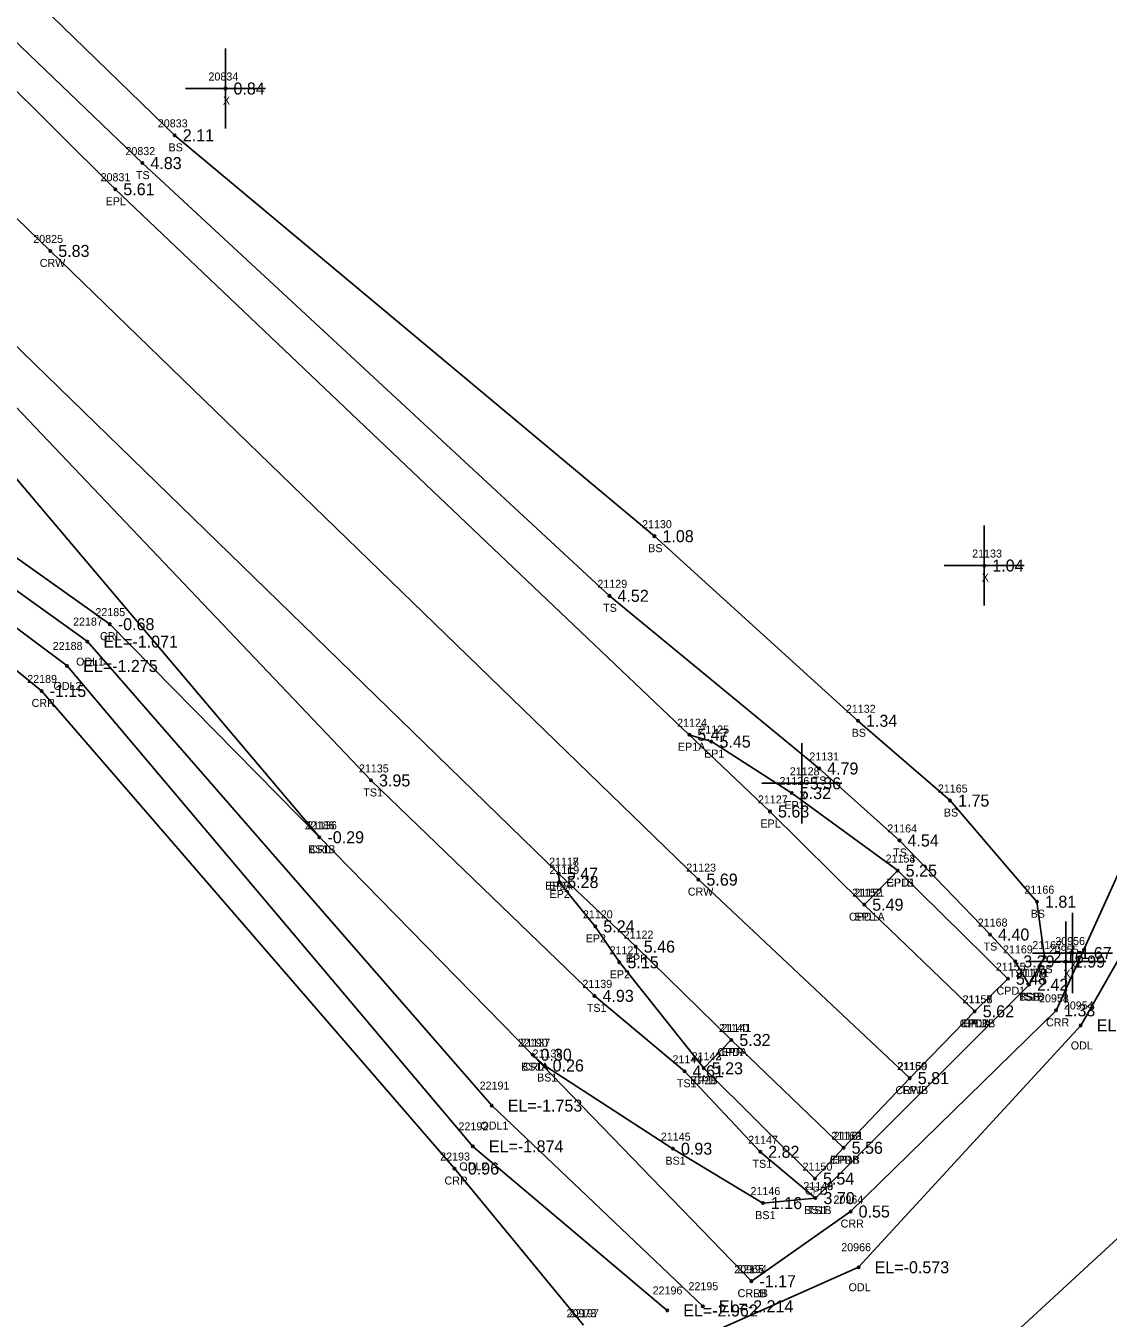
# Model space of a CAD drawing. Extents: x 2608745 to 2610333, y 641917 to 643463.
# Drawn here: x 2609407.7 to 2609542.9, y 642665.2 to 642826.6 of the extents above; entities that cross this region are included whole.
import ezdxf

# ---------------------------------------------------------------- set-up
doc = ezdxf.new("R2010")
doc.units = 0
for name, color, linetype in [('RD_DTM_BkLn1', 7, 'Continuous'), ('RD_DTM_BkLn2', 7, 'Continuous'), ('RD_DTM_BkLn_txCode', 7, 'Continuous'), ('RD_EX_Conc', 7, 'Continuous'), ('RD_EX_Conc_txCode', 7, 'Continuous'), ('RD_EX_H2O', 7, 'Continuous'), ('RD_EX_H2O_txCode', 7, 'Continuous'), ('RD_EX_Misc', 7, 'Continuous'), ('RD_EX_Misc_txCode', 7, 'Continuous'), ('RD_EX_Road', 7, 'Continuous'), ('RD_EX_Road_txCode', 7, 'Continuous'), ('RD_EX_TX_Conc_ELEV', 7, 'Continuous'), ('RD_EX_TX_H2O_ELEV', 7, 'Continuous'), ('RD_EX_TX_Misc_ELEV', 7, 'Continuous'), ('RD_EX_TX_Road_ELEV', 7, 'Continuous'), ('RD_HC_Survey_ELEV', 7, 'Continuous'), ('RD_HC_Survey_txCode', 7, 'Continuous'), ('RD_SMD_Locator', 7, 'Continuous')]:
    doc.layers.add(name, color=color, linetype=linetype)

msp = doc.modelspace()

# ---------------------------------------------------------------- linework, layer by layer
at = {"layer": 'RD_DTM_BkLn1'}
msp.add_lwpolyline([(2608814.73, 643373.65), (2608890.45, 643300.26), (2608962.19, 643231.31), (2609034.91, 643161.19), (2609108.48, 643089.9), (2609179.19, 643022.29), (2609255.71, 642948.78), (2609335.19, 642871.73), (2609410.7, 642798.48), (2609491.67, 642719.95), (2609518.07, 642695.15)], dxfattribs=at)
at = {"layer": 'RD_DTM_BkLn2'}
for points in [[(2609298.5, 642957.84), (2609303.58, 642944.57), (2609301.78, 642940.67), (2609288.09, 642950.22), (2609286.42, 642948.37), (2609286.98, 642943.32), (2609297.07, 642935.45), (2609305.3, 642928.41), (2609313.77, 642918.5), (2609346.23, 642882.3), (2609422.21, 642809.45), (2609480.56, 642755.4), (2609506.75, 642733.83), (2609516.79, 642724.84), (2609528.1, 642713.09), (2609531.25, 642709.73), (2609532.97, 642706.82)], [(2609299.18, 642957.88), (2609318.45, 642940.41), (2609325.58, 642932.79), (2609321.98, 642922.91), (2609316.71, 642922.45), (2609350.68, 642886.23), (2609426.26, 642812.92), (2609486.18, 642762.85), (2609511.6, 642739.79), (2609523.11, 642729.83), (2609533.96, 642717.19), (2609534.91, 642710.27), (2609532.97, 642706.82)], [(2609261.87, 642916.52), (2609266.58, 642914.91), (2609285.18, 642896.17), (2609323.43, 642858.86), (2609399.07, 642786.65), (2609450.77, 642732.34), (2609478.69, 642705.43), (2609489.94, 642696.01), (2609499.39, 642685.95), (2609506.29, 642680.17), (2609532.97, 642706.82)], [(2609260.59, 642912.35), (2609267.04, 642908.29), (2609268.14, 642909.06), (2609282.93, 642892.55), (2609320.01, 642855.03), (2609395.77, 642782.61), (2609444.33, 642725.24)], [(2609470.95, 642698.08), (2609472.46, 642696.73), (2609488.49, 642686.34), (2609499.72, 642679.54), (2609506.29, 642680.17)]]:
    msp.add_lwpolyline(points, dxfattribs=at)
at = {"layer": 'RD_EX_Conc'}
for points in [[(2609512.38, 642716.82), (2609516.56, 642721.08), (2609530.33, 642707.57), (2609526.19, 642703.5)], [(2609495.78, 642699.92), (2609492.33, 642696.38), (2609506.23, 642682.6), (2609509.81, 642686.45)]]:
    msp.add_lwpolyline(points, dxfattribs=at)
at = {"layer": 'RD_EX_H2O'}
for points in [[(2609918.81, 643009.04), (2609840.99, 642946.19), (2609752.78, 642894.89), (2609679.02, 642833.68), (2609605.53, 642770.83), (2609557.42, 642733.27), (2609539.43, 642701.73), (2609511.68, 642671.53), (2609423.05, 642632.06), (2609369.55, 642600.24), (2609327.57, 642579.96), (2609257.07, 642528.8), (2609194.6, 642443.8), (2609156.56, 642341.27)], [(2609920.46, 642991.11), (2609852.12, 642929.11), (2609767.83, 642874.99), (2609693.3, 642807.6), (2609634.08, 642753.09), (2609556.79, 642686.91), (2609524.97, 642657.54), (2609444.81, 642602.16), (2609373.09, 642552.33), (2609285.68, 642492.71), (2609230.49, 642411.33), (2609205.38, 642280.88)], [(2609601.98, 642935.78), (2609673.88, 642833.93), (2609600.06, 642773.78), (2609552.45, 642739.01), (2609536.34, 642703.62), (2609510.68, 642678.49), (2609498.28, 642669.79)], [(2609341.7, 642811.8), (2609348.04, 642813.82), (2609381.33, 642778.02), (2609418.14, 642751.86), (2609444.33, 642725.24), (2609470.95, 642698.08), (2609498.28, 642669.79)], [(2609341.7, 642811.8), (2609340.78, 642806.36), (2609373.72, 642772.7), (2609409.62, 642743.52), (2609461.2, 642683.86), (2609477.32, 642664.29)], [(2609341.7, 642811.8), (2609343.44, 642808.27), (2609375.68, 642774.38), (2609412.81, 642746.64), (2609463.49, 642686.63), (2609487.77, 642666.13)], [(2609341.7, 642811.8), (2609345.04, 642810.74), (2609378.85, 642775.89), (2609415.34, 642749.68), (2609465.85, 642691.72), (2609492.22, 642666.66)]]:
    msp.add_lwpolyline(points, dxfattribs=at)
at = {"layer": 'RD_EX_Misc'}
for p, q in [((2609432.59, 642813.77), (2609432.59, 642823.77)), ((2609427.59, 642818.77), (2609437.59, 642818.77)), ((2609527.38, 642754.18), (2609527.38, 642764.18)), ((2609522.38, 642759.18), (2609532.38, 642759.18)), ((2609504.59, 642726.98), (2609504.59, 642736.98)), ((2609499.59, 642731.98), (2609509.59, 642731.98)), ((2609537.56, 642704.71), (2609537.56, 642714.71)), ((2609538.39, 642705.78), (2609538.39, 642715.78)), ((2609533.39, 642710.78), (2609543.39, 642710.78)), ((2609532.56, 642709.71), (2609542.56, 642709.71))]:
    msp.add_line(p, q, dxfattribs=at)
at = {"layer": 'RD_EX_Road'}
for points in [[(2608806.89, 643364.99), (2608810.18, 643361.1), (2608820.75, 643351.25), (2608881.81, 643292.24), (2608917.83, 643257.49), (2608933.21, 643242.71), (2608954.07, 643222.83), (2609026.06, 643154.19), (2609039.6, 643139.96), (2609073.88, 643106.95), (2609100.48, 643081.89), (2609124.19, 643058.87), (2609171.61, 643013.71), (2609183.19, 643002.28), (2609197.91, 642988.37), (2609247.59, 642940.95), (2609328.02, 642863.6), (2609402.61, 642790.3), (2609474.23, 642720.69), (2609483.84, 642711.58), (2609495.78, 642699.92), (2609509.81, 642686.45)], [(2609058.51, 643155.46), (2609096.06, 643119.37), (2609116.51, 643099.11), (2609162.4, 643055.35), (2609177.21, 643041.34), (2609188.35, 643030.96), (2609199.91, 643019.76), (2609205.8, 643014.04), (2609217.13, 643003.17), (2609235.83, 642983.9), (2609237.03, 642983.51), (2609256.8, 642965.04), (2609258.49, 642962.51), (2609263.65, 642957.66), (2609344.71, 642879.89), (2609418.83, 642806.19), (2609500.61, 642728.46), (2609512.38, 642716.82), (2609526.19, 642703.5)], [(2609490.52, 642738.05), (2609493.3, 642737.2), (2609503.33, 642730.76), (2609516.56, 642721.08)], [(2609474.23, 642720.69), (2609474.28, 642719.65), (2609478.79, 642714.11), (2609481.8, 642709.62), (2609492.33, 642696.38)], [(2609526.19, 642703.5), (2609518.07, 642695.15), (2609509.81, 642686.45)]]:
    msp.add_lwpolyline(points, dxfattribs=at)
at = {"layer": 'RD_SMD_Locator'}
for centre in [(2609432.59, 642818.77), (2609426.26, 642812.92), (2609422.21, 642809.45), (2609418.83, 642806.19), (2609410.7, 642798.48), (2609486.18, 642762.85), (2609527.38, 642759.18), (2609480.56, 642755.4), (2609418.14, 642751.86), (2609415.34, 642749.68), (2609412.81, 642746.64), (2609409.62, 642743.52), (2609511.6, 642739.79), (2609490.52, 642738.05), (2609493.3, 642737.2), (2609450.77, 642732.34), (2609506.75, 642733.83), (2609503.33, 642730.76), (2609504.59, 642731.98), (2609523.11, 642729.83), (2609500.61, 642728.46), (2609444.33, 642725.24), (2609444.33, 642725.24), (2609516.79, 642724.84), (2609516.56, 642721.08), (2609516.56, 642721.08), (2609474.23, 642720.69), (2609474.23, 642720.69), (2609474.28, 642719.65), (2609491.67, 642719.95), (2609512.38, 642716.82), (2609512.38, 642716.82), (2609533.96, 642717.19), (2609478.79, 642714.11), (2609528.1, 642713.09), (2609483.84, 642711.58), (2609531.25, 642709.73), (2609534.91, 642710.27), (2609537.56, 642709.71), (2609538.39, 642710.78), (2609481.8, 642709.62), (2609530.33, 642707.57), (2609532.97, 642706.82), (2609532.97, 642706.82), (2609532.97, 642706.82), (2609478.69, 642705.43), (2609526.19, 642703.5), (2609526.19, 642703.5), (2609526.19, 642703.5), (2609536.34, 642703.62), (2609539.43, 642701.73), (2609495.78, 642699.92), (2609495.78, 642699.92), (2609470.95, 642698.08), (2609470.95, 642698.08), (2609472.46, 642696.73), (2609489.94, 642696.01), (2609492.33, 642696.38), (2609492.33, 642696.38), (2609518.07, 642695.15), (2609518.07, 642695.15), (2609465.85, 642691.72), (2609463.49, 642686.63), (2609488.49, 642686.34), (2609499.39, 642685.95), (2609509.81, 642686.45), (2609509.81, 642686.45), (2609509.81, 642686.45), (2609461.2, 642683.86), (2609506.23, 642682.6), (2609499.72, 642679.54), (2609506.29, 642680.17), (2609506.29, 642680.17), (2609510.68, 642678.49), (2609511.68, 642671.53), (2609498.28, 642669.79), (2609498.28, 642669.79), (2609487.77, 642666.13), (2609492.22, 642666.66)]:
    msp.add_circle(centre, 0.15, dxfattribs=at)

# ---------------------------------------------------------------- texts
at = {"layer": 'RD_DTM_BkLn_txCode'}
for s, p in [('20833', (2609424.14, 642813.92)), ('BS', (2609425.48, 642810.92)), ('20832', (2609420.09, 642810.45)), ('TS', (2609421.41, 642807.45)), ('21130', (2609484.63, 642763.85)), ('BS', (2609485.4, 642760.85)), ('21129', (2609479.05, 642756.4)), ('TS', (2609479.77, 642753.4)), ('21132', (2609510.09, 642740.79)), ('BS', (2609510.82, 642737.79)), ('21131', (2609505.52, 642734.83)), ('21135', (2609449.26, 642733.34)), ('TS', (2609505.95, 642731.83)), ('TS1', (2609449.81, 642730.34)), ('21165', (2609521.58, 642730.83)), ('BS', (2609522.33, 642727.83)), ('21136', (2609442.79, 642726.24)), ('21164', (2609515.26, 642725.84)), ('BS1B', (2609442.91, 642723.24)), ('TS', (2609516, 642722.84)), ('21166', (2609532.4, 642718.19)), ('21168', (2609526.56, 642714.09)), ('BS', (2609533.18, 642715.19)), ('TS', (2609527.3, 642711.09)), ('21169', (2609529.72, 642710.73)), ('21167', (2609533.37, 642711.27)), ('TS', (2609530.46, 642707.73)), ('21170', (2609531.42, 642707.82)), ('21172', (2609531.46, 642707.82)), ('21171', (2609531.74, 642707.82)), ('BS', (2609534.13, 642708.27)), ('21139', (2609477.18, 642706.43)), ('TS1B', (2609531.54, 642704.82)), ('TSB', (2609531.7, 642704.82)), ('BSB', (2609531.72, 642704.82)), ('TS1', (2609477.73, 642703.43)), ('21137', (2609469.44, 642699.08)), ('21138', (2609470.95, 642697.73)), ('BS1A', (2609469.52, 642696.08)), ('21144', (2609488.43, 642697.01)), ('BS1', (2609471.51, 642694.73)), ('TS1', (2609488.98, 642694.01)), ('21145', (2609486.98, 642687.34)), ('21147', (2609497.88, 642686.95)), ('BS1', (2609487.55, 642684.34)), ('TS1', (2609498.43, 642683.95)), ('21146', (2609498.18, 642680.54)), ('21148', (2609504.78, 642681.17)), ('21149', (2609504.78, 642681.17)), ('BS1B', (2609504.87, 642678.17)), ('TS1', (2609505.33, 642678.17)), ('BS1', (2609498.77, 642677.54))]:
    msp.add_text(s, height=1, dxfattribs=at).set_placement(p)
at = {"layer": 'RD_EX_Conc_txCode'}
for s, p in [('21153', (2609515.05, 642722.08)), ('CPD1', (2609515.15, 642719.08)), ('21152', (2609510.87, 642717.82)), ('CPD1A', (2609510.47, 642714.82)), ('21155', (2609528.82, 642708.57)), ('21156', (2609524.66, 642704.5)), ('CPD1', (2609528.91, 642705.57)), ('21141', (2609494.55, 642700.92)), ('CPD1B', (2609524.3, 642701.5)), ('CPDA', (2609494.04, 642697.92)), ('21142', (2609490.82, 642697.38)), ('CPD', (2609491.08, 642694.38)), ('21163', (2609508.27, 642687.45)), ('21150', (2609504.68, 642683.6)), ('CPDB', (2609508.08, 642684.45)), ('CPD', (2609504.97, 642680.6))]:
    msp.add_text(s, height=1, dxfattribs=at).set_placement(p)
at = {"layer": 'RD_EX_H2O_txCode'}
for s, p in [('22185', (2609416.34, 642752.86)), ('22187', (2609413.55, 642751.68)), ('CRL', (2609416.91, 642749.86)), ('22188', (2609411.01, 642748.64)), ('ODL1', (2609413.93, 642746.68)), ('22189', (2609407.83, 642744.52)), ('ODL2', (2609411.11, 642743.64)), ('CRR', (2609408.37, 642741.52)), ('22186', (2609442.51, 642726.24)), ('CRL', (2609443.1, 642723.24)), ('20958', (2609534.22, 642704.62)), ('20954', (2609537.32, 642703.73)), ('CRR', (2609535.09, 642701.62)), ('22190', (2609469.12, 642699.08)), ('ODL', (2609538.19, 642698.73)), ('CRL', (2609469.72, 642696.08)), ('22191', (2609464.34, 642693.72)), ('22192', (2609461.7, 642688.63)), ('ODL1', (2609464.44, 642688.72)), ('22193', (2609459.41, 642684.86)), ('ODL2', (2609461.8, 642683.63)), ('CRR', (2609459.95, 642681.86)), ('20964', (2609508.54, 642679.49)), ('CRR', (2609509.43, 642676.49)), ('20966', (2609509.51, 642673.53)), ('20965', (2609496.14, 642670.79)), ('22194', (2609496.49, 642670.79)), ('22195', (2609490.43, 642668.66)), ('ODL', (2609510.43, 642668.53)), ('22196', (2609485.95, 642668.13)), ('CRRB', (2609496.56, 642667.79)), ('CRLB', (2609496.58, 642667.79)), ('20973', (2609475.2, 642665.29)), ('22197', (2609475.53, 642665.29))]:
    msp.add_text(s, height=1, dxfattribs=at).set_placement(p)
at = {"layer": 'RD_EX_Misc_txCode'}
for s, p in [('20834', (2609430.47, 642819.77)), ('X', (2609432.27, 642816.77)), ('21133', (2609525.87, 642760.18)), ('X', (2609527.06, 642757.18)), ('21128', (2609503.08, 642732.98)), ('X', (2609504.28, 642729.98)), ('20955', (2609535.44, 642710.71)), ('20956', (2609536.24, 642711.78)), ('X', (2609537.25, 642707.71)), ('X', (2609538.07, 642708.78))]:
    msp.add_text(s, height=1, dxfattribs=at).set_placement(p)
at = {"layer": 'RD_EX_Road_txCode'}
for s, p in [('20831', (2609416.99, 642807.19)), ('EPL', (2609417.62, 642804.19)), ('21124', (2609489.01, 642739.05)), ('21125', (2609491.78, 642738.2)), ('EP1A', (2609489.11, 642736.05)), ('EP1', (2609492.37, 642735.2)), ('21126', (2609501.8, 642731.76)), ('21127', (2609499.1, 642729.46)), ('EP1', (2609502.41, 642728.76)), ('EPL', (2609499.41, 642726.46)), ('21154', (2609515.05, 642722.08)), ('21117', (2609473.01, 642721.69)), ('21118', (2609473.01, 642721.69)), ('21119', (2609473.05, 642720.65)), ('EP2A', (2609472.54, 642718.69)), ('EPR', (2609473.01, 642718.69)), ('EP1B', (2609515.17, 642719.08)), ('EP2', (2609473.07, 642717.65)), ('21151', (2609511.15, 642717.82)), ('21120', (2609477.24, 642715.11)), ('EPL', (2609511.17, 642714.82)), ('EP2', (2609477.59, 642712.11)), ('21122', (2609482.33, 642712.58)), ('21121', (2609480.57, 642710.62)), ('EPR', (2609482.61, 642709.58)), ('EP2', (2609480.59, 642707.62)), ('21157', (2609524.68, 642704.5)), ('21158', (2609524.68, 642704.5)), ('21140', (2609494.23, 642700.92)), ('EPLB', (2609524.52, 642701.5)), ('EP1A', (2609524.79, 642701.5)), ('EPR', (2609494.55, 642697.92)), ('21143', (2609490.82, 642697.38)), ('21159', (2609516.55, 642696.15)), ('EP2B', (2609490.65, 642694.38)), ('EP1', (2609517.14, 642693.15)), ('21162', (2609508.27, 642687.45)), ('21161', (2609508.56, 642687.45)), ('EPRB', (2609508.11, 642684.45)), ('EP1B', (2609508.41, 642684.45))]:
    msp.add_text(s, height=1, dxfattribs=at).set_placement(p)
at = {"layer": 'RD_EX_TX_Conc_ELEV'}
for s, p in [('5.25', (2609517.56, 642720.33)), ('5.49', (2609513.38, 642716.07)), ('5.48', (2609531.33, 642706.82)), ('5.62', (2609527.19, 642702.75)), ('5.32', (2609496.78, 642699.17)), ('5.23', (2609493.33, 642695.63)), ('5.56', (2609510.81, 642685.7)), ('5.54', (2609507.23, 642681.85))]:
    msp.add_text(s, height=1.5, dxfattribs=at).set_placement(p)
at = {"layer": 'RD_EX_TX_H2O_ELEV'}
for s, p in [('-0.68', (2609419.14, 642751.11)), ('EL=-1.071', (2609417.34, 642748.93)), ('EL=-1.275', (2609414.81, 642745.89)), ('-1.15', (2609410.62, 642742.77)), ('-0.29', (2609445.33, 642724.49)), ('1.33', (2609537.34, 642702.87)), ('EL=-0.187', (2609541.43, 642700.98)), ('0.30', (2609471.95, 642697.33)), ('EL=-1.753', (2609467.85, 642690.97)), ('EL=-1.874', (2609465.49, 642685.88)), ('-0.96', (2609462.2, 642683.11)), ('0.55', (2609511.68, 642677.74)), ('EL=-0.573', (2609513.68, 642670.78)), ('-1.17', (2609499.28, 642669.04)), ('-1.17', (2609499.28, 642669.04)), ('EL=-2.962', (2609489.77, 642665.38)), ('EL=-2.214', (2609494.22, 642665.91))]:
    msp.add_text(s, height=1.5, dxfattribs=at).set_placement(p)
at = {"layer": 'RD_EX_TX_Misc_ELEV'}
for s, p in [('0.84', (2609433.59, 642818.02)), ('2.11', (2609427.26, 642812.17)), ('4.83', (2609423.21, 642808.7)), ('1.08', (2609487.18, 642762.1)), ('1.04', (2609528.38, 642758.43)), ('4.52', (2609481.56, 642754.65)), ('1.34', (2609512.6, 642739.04)), ('4.79', (2609507.75, 642733.08)), ('3.95', (2609451.77, 642731.59)), ('5.36', (2609505.59, 642731.23)), ('1.75', (2609524.11, 642729.08)), ('-0.29', (2609445.33, 642724.49)), ('4.54', (2609517.79, 642724.09)), ('1.81', (2609534.96, 642716.44)), ('4.40', (2609529.1, 642712.34)), ('1.67', (2609539.39, 642710.03)), ('3.29', (2609532.25, 642708.98)), ('2.16', (2609535.91, 642709.52)), ('1.99', (2609538.56, 642708.96)), ('2.42', (2609533.97, 642706.07)), ('2.42', (2609533.97, 642706.07)), ('2.42', (2609533.97, 642706.07)), ('4.93', (2609479.69, 642704.68)), ('0.30', (2609471.95, 642697.33)), ('0.26', (2609473.46, 642695.98)), ('4.61', (2609490.94, 642695.26)), ('0.93', (2609489.49, 642685.59)), ('2.82', (2609500.39, 642685.2)), ('3.70', (2609507.29, 642679.42)), ('3.70', (2609507.29, 642679.42)), ('1.16', (2609500.72, 642678.79))]:
    msp.add_text(s, height=1.5, dxfattribs=at).set_placement(p)
at = {"layer": 'RD_EX_TX_Road_ELEV'}
for s, p in [('5.61', (2609419.83, 642805.44)), ('5.47', (2609491.52, 642737.3)), ('5.45', (2609494.3, 642736.45)), ('5.32', (2609504.33, 642730.01)), ('5.63', (2609501.61, 642727.71)), ('5.47', (2609475.23, 642719.94)), ('5.47', (2609475.23, 642719.94)), ('5.25', (2609517.56, 642720.33)), ('5.28', (2609475.28, 642718.9)), ('5.49', (2609513.38, 642716.07)), ('5.24', (2609479.79, 642713.36)), ('5.46', (2609484.84, 642710.83)), ('5.15', (2609482.8, 642708.87)), ('5.62', (2609527.19, 642702.75)), ('5.62', (2609527.19, 642702.75)), ('5.32', (2609496.78, 642699.17)), ('5.23', (2609493.33, 642695.63)), ('5.81', (2609519.07, 642694.4)), ('5.56', (2609510.81, 642685.7)), ('5.56', (2609510.81, 642685.7))]:
    msp.add_text(s, height=1.5, dxfattribs=at).set_placement(p)
at = {"layer": 'RD_HC_Survey_ELEV'}
for s, p in [('5.83', (2609411.7, 642797.73)), ('5.69', (2609492.67, 642719.2)), ('5.81', (2609519.07, 642694.4))]:
    msp.add_text(s, height=1.5, dxfattribs=at).set_placement(p)
at = {"layer": 'RD_HC_Survey_txCode'}
for s, p in [('20825', (2609408.58, 642799.48)), ('CRW', (2609409.39, 642796.48)), ('21123', (2609490.15, 642720.95)), ('CRW', (2609490.35, 642717.95)), ('21160', (2609516.49, 642696.15)), ('CRWB', (2609516.28, 642693.15))]:
    msp.add_text(s, height=1, dxfattribs=at).set_placement(p)

doc.saveas('drawing.dxf')
